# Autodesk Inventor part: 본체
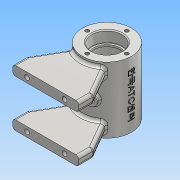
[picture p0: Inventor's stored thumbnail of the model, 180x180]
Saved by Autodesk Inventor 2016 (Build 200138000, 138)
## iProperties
Created: 2018-05
Part Number: 본체
Material: 알루미늄 6061
Document SubType Name: Modeling
Designer: Administrator
Density: 2.7 g/cm^3
Appearance: 알루미늄 - 평지
Mass: 315.562 g
Surface Area: 378.995 cm^2
Volume: 116.875 cm^3
Author: Administrator
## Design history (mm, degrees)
sketch "스케치1"
  geometry: L1 (0, 0)-(0, -70); L2 (0, 0)-(26, 0); L3 (26, 0)-(26, -70); L4 (26, -70)-(0, -70)
  constraints: 8 end point, 2 vertical, 1 horizontal
  dimensions: "d0" = 70 distance of L1.start L1.end; "d1" = 70 distance of L2.end L3.end; "d2" = 52 diameter of L3 L1
revolve "회전1" sketch "스케치1" stored, may be unused: angle "d3" = 90 deg
node "작업 평면1"
node "작업 평면2"
node "작업 평면3"
sketch "스케치2"
  geometry: L1 (0, 0)-(0, -103.85); L2 (-35, -65)-(35, -65); L3 (0, 0)-(20.203, 0); L4 (35, -65)-(35, -50); L5 (35, -50)-(17.325, -19.386); L6 (-35, -65)-(-35, -50); L7 (-35, -50)-(-17.325, -19.386); A1 r 26 centre (0, 0) between (17.325, -19.386) and (-17.325, -19.386) reference; A2 r 26 centre (0, 0) between (-17.325, -19.386) and (17.325, -19.386); 3 further points
  constraints: 14 end point, 4 point on circle, 3 vertical, 2 horizontal, 2 point on line, 1 centre point, 1 midpoint
  dimensions: "d8" = 65 vertical distance of L2.end L3.end; "d9" = 70 distance of L2.start L2.end; "d10" = 15 distance of L2.end L4.end; "d11" = 30 deg angle of L4 L5; "d12" = 15 distance of L2.start L6.end; "d13" = 30 deg angle of L6 L7
extrude "돌출1" join sketch "스케치2" distance "d14" = 10; taper "d15" = 0 deg
sketch "스케치3"
  geometry: L1 (0, 0)-(70, 0) reference; L2 (70, 0)-(70, 10) reference; L3 (0, 10)-(70, 10) reference; L4 (0, 0)-(0, 10) reference; L5 (9, 15)-(61, 15) reference; L6 (9, -55)-(61, -55) reference; L7 (0, -40)-(70, -40) reference; L8 (0, -50)-(70, -50) reference; L9 (35, 15)-(35, -55); L10 (55, 22.355)-(55, -60.469); L11 (15, 19.937)-(15, -63.895); L12 (77.307, 5)-(-12.167, 5); L13 (77.307, -45)-(-22.445, -45); C1 r 2.5 at (15, 5); C2 r 2.5 at (55, 5); C3 r 2.5 at (55, -45); C4 r 2.5 at (15, -45)
  constraints: 10 end point, 8 point on line, 4 centre point, 2 horizontal, 2 vertical, 1 midpoint
  dimensions: "d16" = 20 horizontal distance of L10.end L9.end; "d17" = 20 horizontal distance of L11.end L9.end; "d18" = 5 distance between parallel lines of L3 L12; "d19" = 5 distance between parallel lines of L8 L13; "d20" = 5 diameter of C1; "d21" = 5 diameter of C2; "d22" = 5 diameter of C3; "d23" = 5 diameter of C4
hole "구멍1" sketch "스케치3" at (15, 5), (55, 5), (55, -45), (15, -45) diameter "d24" = 5; stored, may be unused: countersink angle "d28" = 90 deg, drill point angle "d30" = 118 deg; dims "d25" = 6, "d26" = 4, "d27" = 2, "d29" = 10
feature "스레드1" dims "d31" = 8, "d32" = 0
feature "스레드2" dims "d33" = 8, "d34" = 0
feature "스레드3" dims "d35" = 8, "d36" = 0
feature "스레드4" dims "d37" = 8, "d38" = 0
node "작업 평면4"
sketch "스케치4"
  geometry: L1 (3.602, 24.887)-(3.602, -24.887); L2 (3.602, -24.887)-(-3.602, -24.887); L3 (-3.602, -24.887)-(-3.602, 24.887); L4 (-3.602, 24.887)-(3.602, 24.887); L5 (-19.386, -20)-(-19.386, -30) reference; L6 (-19.386, -30)-(-19.386, -30) reference; L7 (-19.386, -30)-(-19.386, -20) reference; L8 (-19.386, -20)-(-19.386, -20) reference; L9 (-19.386, 30)-(-19.386, 20) reference; L10 (-19.386, 20)-(-19.386, 20) reference; L11 (-19.386, 20)-(-19.386, 30) reference; L12 (-19.386, 30)-(-19.386, 30) reference; L13 (-26, 35)-(26, 35) reference; L14 (-26, -35)-(26, -35) reference; L15 (26, 35)-(26, -35) reference; L16 (26, 0)-(0, 0); L17 (-26, 35)-(-26, -35) reference; 1 further point
  constraints: 2 end point, 1 midpoint, 2 other
feature "엠보싱1" sketch "스케치4" dims "d8" = 65, "d9" = 70, "d10" = 15, "d11" = 30 deg, "d12" = 15, "d13" = 30 deg, "d39" = 0.5, "d40" = 0
node "작업 평면6"
  node "작업 평면5"
sketch "스케치5"
  geometry: L1 (-26, 35)-(-26, -35) reference; L2 (-26, -35)-(26, -35) reference; L3 (-26, 35)-(26, 35) reference; L4 (26, 35)-(26, -35) reference; L5 (0, -35)-(0, 0); C1 r 5 at (0, 0); 1 further point
  constraints: 2 end point, 1 centre point, 1 coincident, 1 midpoint
  dimensions: "d42" = 10 diameter of C1
extrude "돌출2" join sketch "스케치5" distance "d43" = 20; taper "d44" = 0 deg
node "작업 평면7"
sketch "스케치6"
  geometry: L1 (5, 29)-(-5, 29) reference; L2 (0, 29)-(0, -23.345); L3 (0, 0)-(-8.893, -24.432); L4 (-4.593, -29.207)-(-9.924, -27.267); L5 (-4.593, -29.207)-(-3.347, -25.784); L6 (-9.924, -27.267)-(-8.893, -24.432); A1 r 26 centre (0, 0) between (17.325, -19.386) and (-17.325, -19.386) reference; A2 r 26 centre (0, 0) between (-17.325, -19.386) and (17.325, -19.386) reference; 1 further point
  constraints: 10 end point, 3 point on circle, 1 midpoint, 1 perpendicular, 1 point on line, 1 vertical
  dimensions: "d47" = 20 deg angle of L2 L3; "d54" = 27.26656 vertical distance of L4.end point (0, 0); "d57" = 11.3474 diameter of L5 L3
revolve "회전2" sketch "스케치6" stored, may be unused: angle "d58" = 90 deg
node "작업 평면8"
sketch "스케치8"
  geometry: L1 (-15, 39)-(-15, 91) reference; L2 (55, 39)-(55, 91) reference; L3 (-15, 65)-(55, 65); L4 (-15, 81)-(-3.3, 81); L5 (-3, 80.7)-(-3, 79); L6 (-3, 79)-(-1, 79); L7 (-1, 79)-(-1, 83); L8 (2, 86)-(38, 86); L9 (55, 81)-(43.3, 81); L10 (43, 80.7)-(43, 79); L11 (43, 79)-(41, 79); L12 (41, 83)-(41, 79); A1 r 0.3 centre (-3.3, 80.7) between (-3, 80.7) and (-3.3, 81); A2 r 0.3 centre (43.3, 80.7) between (43.3, 81) and (43, 80.7); A3 r 3 centre (38, 83) between (41, 83) and (38, 86); A4 r 3 centre (2, 83) between (2, 86) and (-1, 83); 4 further points
  constraints: 20 end point, 10 point on line, 8 point on circle, 8 tangent, 4 centre point, 3 perpendicular, 3 vertical, 2 equal radius, 2 horizontal, 1 midpoint
  dimensions: "d59" = 12 distance of L4.start point (-3, 81); "d60" = 32 diameter of L4 L3; "d61" = 2 distance of L5.end L6.end; "d62" = 28 diameter of L6 L3; "d63" = 42 diameter of L8 L3; "d64" = 42 distance of point (-1, 86) point (41, 86); "d65" = 12 distance of L9.start point (43, 81); "d66" = 32 diameter of L9 L3; "d67" = 2 distance of L10.end L11.end; "d68" = 28 diameter of L11 L3; "d69" = 0.3 radius of A1; "d70" = 3 radius of A3
revolve "회전3" sketch "스케치8" stored, may be unused: angle "d71" = 90 deg
chamfer "모따기1" distance "d72" = 1; stored, may be unused: second distance "d73" = 2, angle "d74" = 45 deg
chamfer "모따기2" distance "d75" = 1; stored, may be unused: second distance "d76" = 2, angle "d77" = 45 deg
sketch "스케치9"
  geometry: C1 r 5.674 at (0, 0) reference; C2 r 3 at (0, 0); 1 further point
  constraints: 1 centre point, 1 coincident
  dimensions: "d78" = 6 diameter of C2
extrude "돌출3" cut sketch "스케치9" stored distance "d79" = 20; taper "d80" = 0 deg
sketch "스케치10"
  geometry: C1 r 5 at (0, 0) reference; C2 r 3 at (0, 0); 1 further point
  constraints: 1 centre point, 1 coincident
  dimensions: "d81" = 6 diameter of C2
extrude "돌출4" cut sketch "스케치10" stored distance "d82" = 20; taper "d83" = 0 deg
feature "스레드5" dims "d84" = 10, "d85" = 0
feature "스레드6" dims "d86" = 10, "d87" = 0
sketch "스케치11" dims "d88" = 42
  geometry: L1 (0, 0)-(-21, 0); C1 r 26 at (0, 0) reference; C2 r 2 at (-21, 0); 1 further point
  constraints: 2 coincident, 2 end point, 1 centre point, 1 horizontal, 1 horizontal alignment, 2 other
  dimensions: "d89" = 4 diameter of C2
hole "구멍2" sketch "스케치11" at (-21, 0) diameter "d90" = 4; stored, may be unused: countersink angle "d94" = 90 deg, drill point angle "d96" = 118 deg; dims "d91" = 6, "d92" = 4, "d93" = 2, "d95" = 10
node "작업 평면9"
feature "스레드7" dims "d100" = 8, "d101" = 0
feature "스레드8" dims "d102" = 8, "d103" = 0
feature "스레드9" dims "d104" = 8, "d105" = 0
feature "스레드10" dims "d106" = 8, "d107" = 0
feature "스레드11" dims "d108" = 8, "d109" = 0
feature "스레드12" dims "d110" = 8, "d111" = 0
feature "스레드13" dims "d112" = 8, "d113" = 0
feature "스레드14" dims "d114" = 8, "d115" = 0
fillet "모깎기3" dims "d118" = 3
fillet "모깎기4" dims "d119" = 2
fillet "모깎기5" dims "d120" = 2
node "솔리드1"
mirror "대칭1"
pattern_circular "원형 패턴1" dims angle "d98" = 360 deg
mirror "대칭2"
node "투영된 루프1"
node "투영된 루프2"
other parameters: "d41" = -3
